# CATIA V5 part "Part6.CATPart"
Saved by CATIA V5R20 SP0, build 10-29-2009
Part number: Part6
Bounding box of the stored display mesh (mm): x 0 to 48, y -10 to 10, z -8.66 to 8.66
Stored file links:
  C:\Users\YS\Desktop\독수리\Part6.CATPart
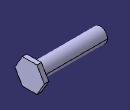
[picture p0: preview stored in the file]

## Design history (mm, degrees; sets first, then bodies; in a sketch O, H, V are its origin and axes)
Body1 (main body)
  Sketch1 on yz-plane, origin (0, 0, 0), H (0, 1, 0), V (0, 0, 1)
    circle A1 centre (0, 0) radius 5
    radius A1 = 5
  Pad1: profile Sketch1, direction (1, 0, 0), length 45
  Sketch2 on end face of Pad1, origin (45, 0, 0), H (0, 1, 0), V (0, 0, 1)
    point P1 (0, 0)
    point P2 (10, 0)
    point P3 (5, 8.6603)
    point P4 (-5, 8.6603)
    point P5 (-10, 0)
    point P6 (-5, -8.6603)
    point P7 (5, -8.6603)
    point P8 (7.5, 4.3301)
    line L1 (10, 0) -> (5, 8.6603)
    line L2 (5, 8.6603) -> (-5, 8.6603)
    line L3 (-5, 8.6603) -> (-10, 0)
    line L4 (-10, 0) -> (-5, -8.6603)
    line L5 (-5, -8.6603) -> (5, -8.6603)
    line L6 (5, -8.6603) -> (10, 0)
    construction line L7 (0, 0) -> (7.5, 4.3301)
    construction circle A1 centre (0, 0) radius 10
    construction arc A2 centre (-5, -8.6603) radius 10 from (-10, 0) to (5, -8.6603) cw
    construction arc A3 centre (5, 8.6603) radius 10 from (-5, 8.6603) to (10, 0) ccw
    length L2 = 10
    coincidence: A1 P2, A1 P3, A1 P4, A1 P5, A1 P6, A1 P7, A2 P1, A3 P1, P1 O
    midpoint: P8 L1
    parallelism: L1 L4
    horizontal: L2 H
  Pad2: profile Sketch2, direction (1, 0, 0), length 3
